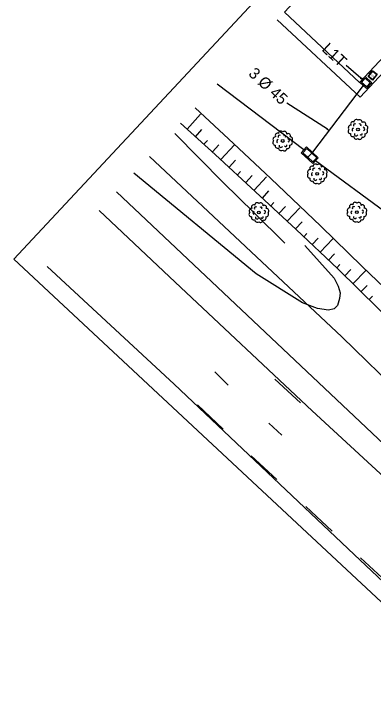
# Model space of a CAD drawing. Extents: x 343997 to 344255, y 298512 to 298767.
# Drawn here: x 343997.3 to 344029, y 298621.1 to 298682.3 of the extents above; entities that cross this region are included whole.
import ezdxf

# ---------------------------------------------------------------- set-up
doc = ezdxf.new("R2010")
doc.units = 0
for name, color, linetype in [('Default', 7, 'Continuous'), ('DH_CADRE -CARTOUCHE', 7, 'Continuous'), ('DIR-Projet VRD1', 7, 'Continuous'), ('EL-coffret', 7, 'Continuous'), ('GO_DALLE', 7, 'Continuous'), ('IMM_VOIRIE VOIE FERREE', 7, 'Continuous'), ('O-Projet New VRD', 7, 'Continuous'), ('PC_REBAR', 7, 'Continuous'), ('PS_HATCH', 7, 'Continuous'), ('PS_OBJECT', 7, 'Continuous'), ('PS_WELD', 7, 'Continuous'), ('RES_ELECTRICITE', 7, 'Continuous'), ('RES_TELEPHONE SOUTERRAIN', 7, 'Continuous')]:
    doc.layers.add(name, color=color, linetype=linetype)

# ---------------------------------------------------------------- blocks, each defined once
blk = doc.blocks.new('RES_ELECTRICITE')
at = {"layer": 'RES_ELECTRICITE'}
for points in [[(0, 0), (0, 0.1), (0.1, 0.1), (0.1, 0)], [(0.005, 0.005), (0.005, 0.095), (0.095, 0.095), (0.095, 0.005)]]:
    blk.add_lwpolyline(points, close=True, dxfattribs=at)
blk.add_text('EEC', height=0.02, dxfattribs=at).set_placement((0.0237, 0.046))
blk = doc.blocks.new('ARB1')
at = {"layer": 'Default'}
blk.add_circle((0, 0), 0.0122, dxfattribs=at)
for centre, radius, start, end in [((-0.0471, 0.0503), 0.0183, 53.95544, 222.20655), ((-0.0153, 0.0664), 0.0211, 43.69255, 183.5969), ((0.0139, 0.0613), 0.0241, 358.45835, 125.19284), ((0.0501, 0.0468), 0.0183, 325.14445, 131.01755), ((-0.0613, 0.0139), 0.0241, 88.45835, 215.19284), ((-0.0373, -0.0024), 0.0149, 103.70924, 242.34652), ((-0.0276, 0.037), 0.0134, 52.43963, 209.54959), ((0.0164, 0.038), 0.0112, 330.58954, 133.71274), ((0.0458, 0.0052), 0.0137, 276.62143, 88.96702), ((0.0613, -0.0139), 0.0241, 268.45835, 35.19284), ((0.0664, 0.0153), 0.0211, 313.69255, 93.5969), ((-0.0664, -0.0153), 0.0211, 133.69255, 273.5969), ((-0.0478, -0.0443), 0.019, 155.22426, 300.93774), ((-0.0139, -0.0613), 0.0241, 178.45835, 305.19284), ((-0.0163, -0.042), 0.0148, 159.53711, 338.16632), ((0.0271, -0.038), 0.0112, 210.58954, 13.71274), ((0.0448, -0.0483), 0.0188, 243.13234, 33.02965), ((0.0153, -0.0664), 0.0211, 223.69255, 3.5969)]:
    blk.add_arc(centre, radius, start, end, dxfattribs=at)

msp = doc.modelspace()

# ---------------------------------------------------------------- linework, layer by layer
at = {"layer": 'DH_CADRE -CARTOUCHE'}
for points in [[(343997.309, 298660.673), (344147.183, 298520.807), (344245.09, 298625.72), (344095.215, 298765.586)], [(344026.391, 298688.063), (344021.173, 298682.472), (344027.812, 298676.264), (344033.029, 298681.855)]]:
    msp.add_lwpolyline(points, close=True, dxfattribs=at)
at = {"layer": 'DIR-Projet VRD1'}
for p, q in [((344022.903, 298670.322), (344015.257, 298676.132)), ((344028.118, 298676), (344023.655, 298670.106)), ((344023.933, 298669.374), (344062.068, 298641.235))]:
    msp.add_line(p, q, dxfattribs=at)
at = {"layer": 'EL-coffret'}
msp.add_lwpolyline([(344028.853, 298677.382), (344028.926, 298677.315), (344028.676, 298677.044), (344028.603, 298677.111)], close=True, dxfattribs=at)
at = {"layer": 'GO_DALLE'}
msp.add_lwpolyline([(344020.546, 298681.8), (344027.856, 298674.963), (344034.929, 298682.543), (344027.611, 298689.371)], dxfattribs=at)
at = {"layer": 'IMM_VOIRIE VOIE FERREE'}
for points in [[(344004.845, 298664.976), (344011.548, 298658.641), (344023.625, 298647.296), (344036.026, 298635.848), (344041.222, 298631.015), (344044.302, 298628.712), (344047.148, 298627.07), (344049.39, 298626.335), (344051.578, 298625.986), (344053.429, 298626.194), (344055.021, 298627.169), (344056.068, 298627.836), (344057.07, 298628.691)], [(344074.933, 298589.956), (344073.98, 298590.843), (344059.741, 298604.247), (344043.778, 298619.111), (344027.338, 298634.596), (344011.457, 298649.631), (344000.234, 298660.034)], [(344016.229, 298649.558), (344015.044, 298650.717)], [(344022.587, 298647.982), (344020.324, 298650.078)], [(344013.497, 298647.809), (344015.776, 298645.68)], [(344020.942, 298645.146), (344019.811, 298646.202)], [(344018.259, 298643.331), (344020.513, 298641.227)], [(344023.058, 298638.846), (344025.391, 298636.664)], [(344027.896, 298634.308), (344030.175, 298632.195)]]:
    msp.add_lwpolyline(points, dxfattribs=at)
at = {"layer": 'O-Projet New VRD'}
for points in [[(344027.924, 298676.646), (344026.624, 298677.771)], [(344028.299, 298676.785), (344028.886, 298676.244), (344028.412, 298675.729), (344027.823, 298676.271), (344028.297, 298676.786)], [(344028.306, 298676.647), (344028.748, 298676.241), (344028.409, 298675.872), (344027.968, 298676.279), (344028.307, 298676.647)], [(344024.967, 298672.136), (344021.399, 298674.447)], [(344023.14, 298670.58), (344024.17, 298669.631), (344023.696, 298669.116), (344022.666, 298670.065), (344023.14, 298670.58)], [(344023.146, 298670.439), (344023.587, 298670.032), (344023.249, 298669.664), (344023.69, 298669.258), (344024.029, 298669.626), (344023.146, 298670.439), (344022.807, 298670.071), (344023.249, 298669.664)]]:
    msp.add_lwpolyline(points, dxfattribs=at)
for points in [[(344027.944, 298676.669), (344028.06, 298676.529), (344027.904, 298676.624)], [(344024.983, 298672.161), (344025.118, 298672.038), (344024.951, 298672.111)]]:
    msp.add_lwpolyline(points, close=True, dxfattribs=at)
at = {"layer": 'PC_REBAR'}
msp.add_lwpolyline([(344011.505, 298671.764), (344015.775, 298667.449), (344018.517, 298664.761), (344021.204, 298662.081)], dxfattribs=at)
at = {"layer": 'PS_HATCH'}
msp.add_lwpolyline([(344022.969, 298661.88), (344025.559, 298658.997), (344025.913, 298658.296), (344026.092, 298657.69), (344026.053, 298657.21), (344025.863, 298656.58), (344025.554, 298656.29), (344025.074, 298656.172), (344024.091, 298656.308), (344022.768, 298656.814), (344018.686, 298659.395), (344007.903, 298668.252)], dxfattribs=at)
at = {"layer": 'PS_OBJECT'}
for p, q in [((344012.595, 298672.149), (344013.783, 298673.471)), ((344013.339, 298671.481), (344013.903, 298672.108)), ((344014.083, 298670.812), (344014.38, 298671.143)), ((344014.826, 298670.143), (344015.392, 298670.772)), ((344015.564, 298669.468), (344016.775, 298670.779)), ((344016.299, 298668.789), (344016.874, 298669.412)), ((344017.034, 298668.111), (344017.307, 298668.407)), ((344017.769, 298667.432), (344018.345, 298668.056)), ((344018.504, 298666.754), (344019.598, 298667.939)), ((344019.236, 298666.072), (344019.817, 298666.694)), ((344019.968, 298665.39), (344020.243, 298665.685)), ((344020.699, 298664.707), (344021.281, 298665.331)), ((344021.43, 298664.025), (344022.535, 298665.209)), ((344022.162, 298663.343), (344022.745, 298663.967)), ((344022.888, 298662.655), (344023.167, 298662.95)), ((344023.614, 298661.967), (344024.144, 298662.527)), ((344024.341, 298661.279), (344025.459, 298662.46)), ((344025.067, 298660.591), (344025.598, 298661.152)), ((344025.793, 298659.903), (344026.073, 298660.199)), ((344026.508, 298659.204), (344027.05, 298659.757)), ((344027.222, 298658.504), (344028.366, 298659.669)), ((344027.936, 298657.803), (344028.479, 298658.357)), ((344028.65, 298657.102), (344028.937, 298657.395))]:
    msp.add_line(p, q, dxfattribs=at)
for points in [[(344013.309, 298674.045), (344016.677, 298670.884), (344019.994, 298667.792), (344024.403, 298663.589), (344028.025, 298660.019), (344032.009, 298656.228), (344035.513, 298652.822), (344038.498, 298649.953), (344041.923, 298646.692), (344044.756, 298643.58), (344054.456, 298635.377)], [(344054.456, 298635.377), (344052.269, 298635.996), (344049.579, 298637.638), (344045.345, 298641.507), (344040.154, 298646.415), (344036.423, 298649.686), (344032.732, 298653.214), (344029.519, 298656.25), (344025.888, 298659.813), (344022.228, 298663.281), (344018.635, 298666.633), (344015.082, 298669.913), (344012.021, 298672.665)]]:
    msp.add_lwpolyline(points, dxfattribs=at)
at = {"layer": 'PS_WELD'}
msp.add_lwpolyline([(344037.247, 298643.122), (344026.234, 298653.823), (344009.284, 298669.732)], dxfattribs=at)
at = {"layer": 'RES_TELEPHONE SOUTERRAIN'}
msp.add_lwpolyline([(344006.37, 298666.609), (344159.504, 298522.019), (344160.824, 298520.82), (344163.6, 298518.226)], dxfattribs=at)

# ---------------------------------------------------------------- block references
at = {"layer": 'PC_REBAR', "xscale": 10, "yscale": 10}
for p in [(344027.67, 298672.123), (344021.025, 298671.108), (344024.075, 298668.2), (344018.928, 298664.786), (344027.574, 298664.82)]:
    msp.add_blockref('ARB1', p, dxfattribs=at)
at = {"layer": 'RES_ELECTRICITE', "xscale": 5.039776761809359, "yscale": 6.650433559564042, "rotation": 140.49315}
msp.add_blockref('RES_ELECTRICITE', (344029.377, 298676.991), dxfattribs=at)

# ---------------------------------------------------------------- texts
at = {"layer": 'O-Projet New VRD'}
for s, p in [('L1T', (344024.411, 298679.126)), ('3 Ø 45', (344017.941, 298676.956))]:
    msp.add_text(s, height=1.0003, rotation=317.36723, dxfattribs=at).set_placement(p)

doc.saveas('drawing.dxf')
